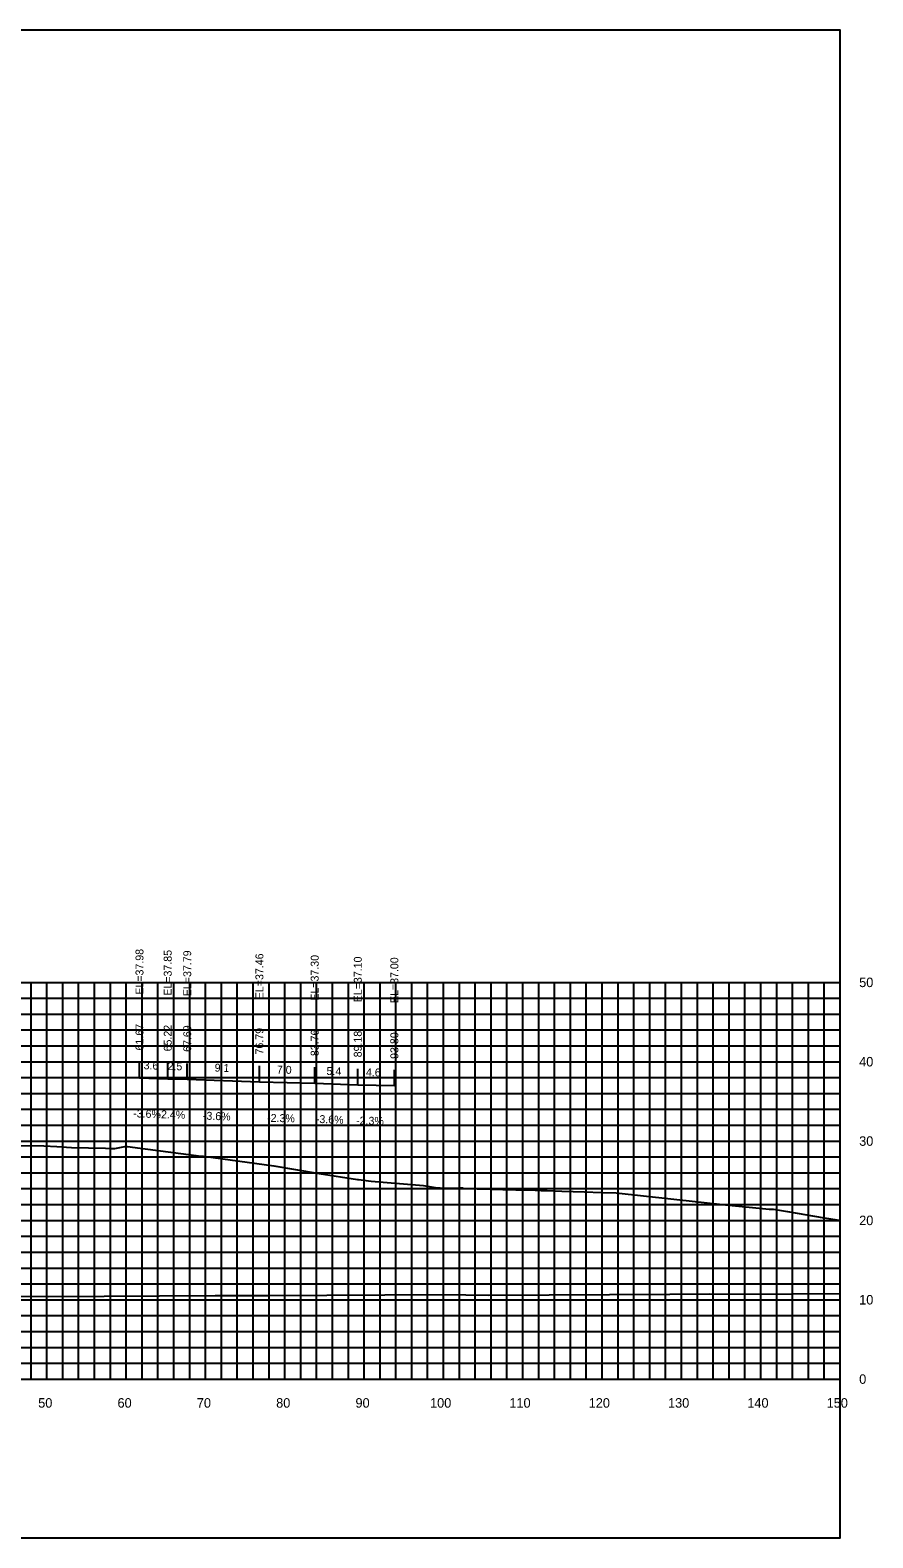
# Model space of a CAD drawing. Extents: x 1800880 to 1818864, y 245271 to 250560.
# Drawn here: x 1810219 to 1810325.3, y 248532.9 to 248722.9 of the extents above; entities that cross this region are included whole.
import ezdxf

# ---------------------------------------------------------------- set-up
doc = ezdxf.new("R2010")
doc.units = 0
for name, color, linetype in [('33', 7, 'Continuous'), ('ANNO-TXT', 7, 'Continuous'), ('CL-CNST', 7, 'Continuous'), ('DESIGN - DRAINAGE - Bridges', 7, 'Continuous'), ('Level 37', 7, 'Continuous'), ('Level 46', 7, 'Continuous'), ('Level 62', 7, 'Continuous'), ('SHT-BDR', 7, 'Continuous')]:
    doc.layers.add(name, color=color, linetype=linetype)

msp = doc.modelspace()

# ---------------------------------------------------------------- linework, layer by layer
at = {"layer": 'CL-CNST'}
msp.add_lwpolyline([(1810214.89, 248582.34), (1810220.74, 248582.28), (1810222.38, 248582.17), (1810224.24, 248582.05), (1810228.53, 248581.96), (1810229.2, 248581.95), (1810229.35, 248581.94), (1810229.6, 248581.94), (1810229.7, 248581.94), (1810230.95, 248582.19), (1810231.02, 248582.19), (1810231.28, 248582.17), (1810240.59, 248580.96), (1810240.87, 248580.96), (1810249.74, 248579.73), (1810255.19, 248578.81), (1810255.47, 248578.77), (1810260.29, 248578.03), (1810260.4, 248578.03), (1810262.02, 248577.82), (1810268.62, 248577.27), (1810270.39, 248576.97), (1810270.43, 248576.97), (1810270.48, 248576.97), (1810270.52, 248576.97), (1810270.56, 248576.96), (1810270.59, 248576.96), (1810270.62, 248576.96), (1810270.66, 248576.96), (1810270.69, 248576.96), (1810270.71, 248576.96), (1810270.74, 248576.95), (1810270.75, 248576.95), (1810273.29, 248576.98), (1810273.52, 248576.96), (1810273.72, 248576.88), (1810280.26, 248576.72), (1810282.67, 248576.66), (1810283.02, 248576.66), (1810283.43, 248576.65), (1810284.19, 248576.62), (1810286.04, 248576.57), (1810288.91, 248576.49), (1810291.04, 248576.4), (1810292.88, 248576.33), (1810306.66, 248574.83), (1810312.19, 248574.29), (1810312.25, 248574.28), (1810312.73, 248574.28), (1810314.49, 248573.98), (1810319.1, 248573.19), (1810319.71, 248573.09), (1810320.99, 248572.88), (1810321.13, 248572.85)], dxfattribs=at)
at = {"layer": 'DESIGN - DRAINAGE - Bridges'}
for p, q in [((1810321.13, 248552.87), (1810321.13, 248602.87)), ((1810321.19, 248602.87), (1810321.13, 248602.87)), ((1810321.19, 248592.87), (1810321.13, 248592.87)), ((1810321.19, 248582.87), (1810321.13, 248582.87)), ((1810321.19, 248572.87), (1810321.13, 248572.87)), ((1810321.19, 248562.87), (1810321.13, 248562.87)), ((1810021.13, 248552.87), (1810321.13, 248552.87)), ((1810221.13, 248552.81), (1810221.13, 248552.87)), ((1810231.13, 248552.81), (1810231.13, 248552.87)), ((1810241.13, 248552.81), (1810241.13, 248552.87)), ((1810251.13, 248552.81), (1810251.13, 248552.87)), ((1810261.13, 248552.81), (1810261.13, 248552.87)), ((1810271.13, 248552.81), (1810271.13, 248552.87)), ((1810281.13, 248552.81), (1810281.13, 248552.87)), ((1810291.13, 248552.81), (1810291.13, 248552.87)), ((1810301.13, 248552.81), (1810301.13, 248552.87)), ((1810311.13, 248552.81), (1810311.13, 248552.87)), ((1810321.13, 248552.81), (1810321.13, 248552.87)), ((1810321.19, 248552.87), (1810321.13, 248552.87))]:
    msp.add_line(p, q, dxfattribs=at)
at = {"layer": 'Level 37'}
for p, q in [((1810232.8, 248590.85), (1810232.8, 248592.85)), ((1810236.36, 248590.72), (1810236.36, 248592.72)), ((1810238.82, 248590.66), (1810238.82, 248592.66)), ((1810247.92, 248590.33), (1810247.92, 248592.33)), ((1810254.89, 248590.17), (1810254.89, 248592.17)), ((1810260.32, 248589.97), (1810260.32, 248591.97)), ((1810264.93, 248589.86), (1810264.93, 248591.86))]:
    msp.add_line(p, q, dxfattribs=at)
msp.add_lwpolyline([(1810021.13, 248532.87), (1810321.13, 248532.87), (1810321.13, 248722.87), (1810021.13, 248722.87)], close=True, dxfattribs=at)
at = {"layer": 'Level 46'}
for p, q in [((1810021.13, 248602.87), (1810321.13, 248602.87)), ((1810219.13, 248552.87), (1810219.13, 248602.87)), ((1810221.13, 248552.87), (1810221.13, 248602.87)), ((1810223.13, 248552.87), (1810223.13, 248602.87)), ((1810225.13, 248552.87), (1810225.13, 248602.87)), ((1810227.13, 248552.87), (1810227.13, 248602.87)), ((1810229.13, 248552.87), (1810229.13, 248602.87)), ((1810231.13, 248552.87), (1810231.13, 248602.87)), ((1810233.13, 248552.87), (1810233.13, 248602.87)), ((1810235.13, 248552.87), (1810235.13, 248602.87)), ((1810237.13, 248552.87), (1810237.13, 248602.87)), ((1810239.13, 248552.87), (1810239.13, 248602.87)), ((1810241.13, 248552.87), (1810241.13, 248602.87)), ((1810243.13, 248552.87), (1810243.13, 248602.87)), ((1810245.13, 248552.87), (1810245.13, 248602.87)), ((1810247.13, 248552.87), (1810247.13, 248602.87)), ((1810249.13, 248552.87), (1810249.13, 248602.87)), ((1810251.13, 248552.87), (1810251.13, 248602.87)), ((1810253.13, 248552.87), (1810253.13, 248602.87)), ((1810255.13, 248552.87), (1810255.13, 248602.87)), ((1810257.13, 248552.87), (1810257.13, 248602.87)), ((1810259.13, 248552.87), (1810259.13, 248602.87)), ((1810261.13, 248552.87), (1810261.13, 248602.87)), ((1810263.13, 248552.87), (1810263.13, 248602.87)), ((1810265.13, 248552.87), (1810265.13, 248602.87)), ((1810267.13, 248552.87), (1810267.13, 248602.87)), ((1810269.13, 248552.87), (1810269.13, 248602.87)), ((1810271.13, 248552.87), (1810271.13, 248602.87)), ((1810273.13, 248552.87), (1810273.13, 248602.87)), ((1810275.13, 248552.87), (1810275.13, 248602.87)), ((1810277.13, 248552.87), (1810277.13, 248602.87)), ((1810279.13, 248552.87), (1810279.13, 248602.87)), ((1810281.13, 248552.87), (1810281.13, 248602.87)), ((1810283.13, 248552.87), (1810283.13, 248602.87)), ((1810285.13, 248552.87), (1810285.13, 248602.87)), ((1810287.13, 248552.87), (1810287.13, 248602.87)), ((1810289.13, 248552.87), (1810289.13, 248602.87)), ((1810291.13, 248552.87), (1810291.13, 248602.87)), ((1810293.13, 248552.87), (1810293.13, 248602.87)), ((1810295.13, 248552.87), (1810295.13, 248602.87)), ((1810297.13, 248552.87), (1810297.13, 248602.87)), ((1810299.13, 248552.87), (1810299.13, 248602.87)), ((1810301.13, 248552.87), (1810301.13, 248602.87)), ((1810303.13, 248552.87), (1810303.13, 248602.87)), ((1810305.13, 248552.87), (1810305.13, 248602.87)), ((1810307.13, 248552.87), (1810307.13, 248602.87)), ((1810309.13, 248552.87), (1810309.13, 248602.87)), ((1810311.13, 248552.87), (1810311.13, 248602.87)), ((1810313.13, 248552.87), (1810313.13, 248602.87)), ((1810315.13, 248552.87), (1810315.13, 248602.87)), ((1810317.13, 248552.87), (1810317.13, 248602.87)), ((1810319.13, 248552.87), (1810319.13, 248602.87)), ((1810321.13, 248552.87), (1810321.13, 248602.87)), ((1810021.13, 248600.87), (1810321.13, 248600.87)), ((1810021.13, 248598.87), (1810321.13, 248598.87)), ((1810021.13, 248596.87), (1810321.13, 248596.87)), ((1810021.13, 248594.87), (1810321.13, 248594.87)), ((1810021.13, 248592.87), (1810321.13, 248592.87)), ((1810021.13, 248590.87), (1810321.13, 248590.87)), ((1810021.13, 248588.87), (1810321.13, 248588.87)), ((1810021.13, 248586.87), (1810321.13, 248586.87)), ((1810021.13, 248584.87), (1810321.13, 248584.87)), ((1810021.13, 248582.87), (1810321.13, 248582.87)), ((1810021.13, 248580.87), (1810321.13, 248580.87)), ((1810021.13, 248578.87), (1810321.13, 248578.87)), ((1810021.13, 248576.87), (1810321.13, 248576.87)), ((1810021.13, 248574.87), (1810321.13, 248574.87)), ((1810021.13, 248572.87), (1810321.13, 248572.87)), ((1810021.13, 248570.87), (1810321.13, 248570.87)), ((1810021.13, 248568.87), (1810321.13, 248568.87)), ((1810021.13, 248566.87), (1810321.13, 248566.87)), ((1810021.13, 248564.87), (1810321.13, 248564.87)), ((1810021.13, 248562.87), (1810321.13, 248562.87)), ((1810021.13, 248560.87), (1810321.13, 248560.87)), ((1810021.13, 248558.87), (1810321.13, 248558.87)), ((1810021.13, 248556.87), (1810321.13, 248556.87)), ((1810021.13, 248554.87), (1810321.13, 248554.87)), ((1810021.13, 248552.87), (1810321.13, 248552.87))]:
    msp.add_line(p, q, dxfattribs=at)
at = {"layer": 'Level 62'}
for points in [[(1810232.8, 248590.85), (1810236.36, 248590.72), (1810238.82, 248590.66), (1810247.92, 248590.33), (1810254.89, 248590.17), (1810260.32, 248589.97), (1810264.93, 248589.86)], [(1810021.13, 248564.16), (1810027.05, 248564.09), (1810033.23, 248564.05), (1810054.8, 248563.84), (1810064.78, 248563.79), (1810082.56, 248563.66), (1810095.44, 248563.62), (1810110.31, 248563.48), (1810125.5, 248563.45), (1810138.07, 248563.37), (1810155.13, 248563.37), (1810165.83, 248563.29), (1810184.43, 248563.32), (1810193.58, 248563.26), (1810213.48, 248563.32), (1810221.34, 248563.3), (1810242.35, 248563.4), (1810249.09, 248563.4), (1810271.06, 248563.53), (1810276.85, 248563.43), (1810299.65, 248563.56), (1810304.6, 248563.61), (1810309.17, 248563.58), (1810321.13, 248563.66)]]:
    msp.add_lwpolyline(points, dxfattribs=at)

# ---------------------------------------------------------------- texts
for s, p in [('50', (1810220.03, 248549.27)), ('60', (1810230.03, 248549.27)), ('70', (1810240.03, 248549.27)), ('80', (1810250.03, 248549.27)), ('90', (1810260.03, 248549.27)), ('100', (1810269.43, 248549.27)), ('110', (1810279.43, 248549.27)), ('120', (1810289.43, 248549.27)), ('130', (1810299.43, 248549.27)), ('140', (1810309.43, 248549.27)), ('150', (1810319.43, 248549.27))]:
    msp.add_text(s, height=1.2).set_placement(p)
at = {"layer": '33'}
for s, p in [('50', (1810323.53, 248602.27)), ('40', (1810323.53, 248592.27)), ('30', (1810323.53, 248582.27)), ('20', (1810323.53, 248572.27)), ('10', (1810323.53, 248562.27)), ('0', (1810323.53, 248552.27))]:
    msp.add_text(s, height=1.2, dxfattribs=at).set_placement(p)
at = {"layer": 'ANNO-TXT'}
for s, rotation, p in [('3.6', 357.9123, (1810233.31, 248591.93)), ('2.5', 358.6406, (1810236.33, 248591.82)), ('9.1', 357.9214, (1810242.26, 248591.63)), ('7.0', 358.665, (1810250.11, 248591.38)), ('5.4', 357.9457, (1810256.36, 248591.21)), ('4.6', 358.6802, (1810261.34, 248591.05)), ('-3.6%', 357.9123, (1810231.99, 248585.87)), ('-2.4%', 358.6406, (1810235.06, 248585.75)), ('-3.6%', 357.9214, (1810240.78, 248585.58)), ('-2.3%', 358.665, (1810248.88, 248585.3)), ('-3.6%', 357.9457, (1810255.02, 248585.16)), ('-2.3%', 358.6802, (1810260.1, 248584.97))]:
    msp.add_text(s, height=1, rotation=rotation, dxfattribs=at).set_placement(p)
at = {"layer": 'SHT-BDR'}
for s, p in [('EL=37.98', (1810233.3, 248601.32)), ('EL=37.85', (1810236.86, 248601.19)), ('EL=37.79', (1810239.32, 248601.13)), ('EL=37.46', (1810248.42, 248600.75)), ('EL=37.30', (1810255.39, 248600.56)), ('EL=37.10', (1810260.82, 248600.36)), ('EL=37.00', (1810265.43, 248600.26)), ('61.67', (1810233.3, 248594.29)), ('65.22', (1810236.86, 248594.17)), ('67.69', (1810239.32, 248594.11)), ('76.79', (1810248.42, 248593.78)), ('83.76', (1810255.39, 248593.57)), ('89.18', (1810260.82, 248593.42)), ('93.80', (1810265.43, 248593.23))]:
    msp.add_text(s, height=1, rotation=90, dxfattribs=at).set_placement(p)

doc.saveas('drawing.dxf')
